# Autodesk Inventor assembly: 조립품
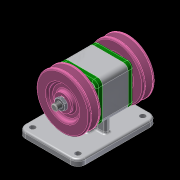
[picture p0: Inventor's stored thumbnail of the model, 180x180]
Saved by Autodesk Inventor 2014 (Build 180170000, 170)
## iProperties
Created: 2020-11
Part Number: 조립품
Document SubType Name: Assembly
Designer: kh
Author: kh
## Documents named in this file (10)
- C:\Users\kh\Desktop\701106V1021\조립품.iam
- C:\Users\kh\Desktop\701106V1021\본체.ipt
- C:\Users\kh\Desktop\701106V1021\베어링 6004.ipt
- C:\Users\kh\Desktop\701106V1021\축.ipt
- C:\Users\kh\Desktop\701106V1021\커버.ipt
- C:\Users\kh\Desktop\701106V1021\오일 실 17 30 5.ipt
- C:\Users\kh\Desktop\701106V1021\키 5 x 5 x 12.ipt
- C:\Users\kh\Desktop\701106V1021\V-벨트풀리.ipt
- C:\Users\kh\Desktop\701106V1021\너트 M10x1.ipt
- C:\Users\kh\Desktop\701106V1021\볼트 M4.ipt
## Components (2 placed, 1 different names)
1. V-벨트풀리:1 — 각도:1
2. V-벨트풀리:2
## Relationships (1: Angle 1)
- 각도:1 [Angle]: V-벨트풀리:1
